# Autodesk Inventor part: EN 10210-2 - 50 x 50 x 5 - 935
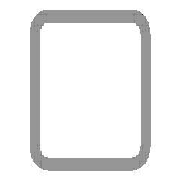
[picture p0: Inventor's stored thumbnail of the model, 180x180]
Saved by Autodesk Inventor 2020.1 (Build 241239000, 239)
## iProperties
IsCustomPart: 1
_CCFamilyMember: 16
_CCFamilyDisplayName: DIN EN 10210-2 (USAS B17.1 quadratisch) - Rohrleitung — In Klammern angegebene Größen wurden aufgehoben
_FrameMemberDoc: Frame Member File
_Version: 15.0.0
_GetPNFromCC: 1
Created: 2019-10
Part Number: EN 10210-2 - 50 x 50 x 5 - 935
Material: Stahl, weich
Description: Rohrleitung
Document SubType Name: Modeling
Standard: DIN
Designer: lutzd
Standard Revision: 2006-07
Standards Organization: DIN
Language: de-DE
Size Designation: 50 x 50 x 5
Categories: <MemberInstance><Categories><Category DisplayName="Profile" InternalName="089c4875-fa83-4c05-b084-43b9cc11f5ed" Mnemonic="GRDR"><CategoryParameter DisplayName="
Stock Number: 50 x 50 x 5
Mass: 6406.16 g
Surface Area: 3183.51 cm^2
Volume: 816.071 cm^3
Density: 7.85 g/cm^3
Appearance: Halbpoliert
G_L: 935,000 mm
G_W: 50,000 mm
G_H: 50,000 mm
Dimensions: 50x50x935 mm
Mass: 6,406 kg
DocNumber: ADSK-014086
Folder: .
+DC350E34-C48C-440D-B476-852694BBE631+SCHNITTDETAIL1: Schnittwinkel 90,00 grd
+4DCEFB5E-3CB5-4DBE-9410-B38ADCC61D04+SCHNITTDETAIL2: Schnittwinkel 90,00 grd
Title: Profil-Bauteil
Author: lutzd
Revision Number: -
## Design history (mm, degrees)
node "Startebene"
node "Endebene"
sketch "Skizze"
  geometry: L1 (-25, -17.5)-(-25, 17.5); L2 (-17.5, 25)-(17.5, 25); L3 (25, 17.5)-(25, -17.5); L4 (17.5, -25)-(-17.5, -25); L5 (-15, 20)-(15, 20); L6 (20, 15)-(20, -15); L7 (15, -20)-(-15, -20); L8 (-20, -15)-(-20, 15); L9 (0, 37.175)-(0, -37.175) reference; L10 (-37.175, 0)-(37.175, 0) reference; A1 r 7.5 centre (-17.5, -17.5) between (-25, -17.5) and (-17.5, -25); A2 r 7.5 centre (-17.5, 17.5) between (-17.5, 25) and (-25, 17.5); A3 r 7.5 centre (17.5, 17.5) between (25, 17.5) and (17.5, 25); A4 r 7.5 centre (17.5, -17.5) between (17.5, -25) and (25, -17.5); A5 r 5 centre (-15, -15) between (-20, -15) and (-15, -20); A6 r 5 centre (-15, 15) between (-15, 20) and (-20, 15); A7 r 5 centre (15, 15) between (20, 15) and (15, 20); A8 r 5 centre (15, -15) between (15, -20) and (20, -15)
  constraints: 16 end point, 16 point on circle, 16 tangent, 8 centre point, 6 equal radius, 4 parallel, 2 perpendicular, 2 other
  dimensions: "d7" = 7.5 radius of A1 (= G_IR); "d10" = 50 distance between parallel lines of L2 L4 (= G_H); "d11" = 50 distance between parallel lines of L1 L3 (= G_W); "d12" = 5 distance between parallel lines of L3 L6 (= G_T); "d15" = 25 distance between parallel lines of L2 L10 (= 0.5 x d10); "d16" = 25 distance between parallel lines of L9 L3 (= 0.5 x d11); "d19" = 5 radius of A5 (= G_T); "d20" = 5 distance between parallel lines of L4 L7 (= G_T)
extrude "Körper" new body sketch "Skizze" stored distance "d3" = 935 (= G_L); taper "d4" = 0 deg
node "Driven Length"
  sketch "Sketch3"
    geometry: L1 (0, 0)-(10, 0) reference
    constraints: 2 end point, 1 horizontal
  workplane "Work Plane3"
  sketch "Sketch4"
    geometry: L1 (-2, 25)-(12, 25) reference; L2 (-2, 960)-(12, 960) reference
    dimensions: "d18" = 935 distance between parallel lines of L1 L2 (derived)
workplane "Arbeitsebene4"
feature "Trennen1"
workplane "Arbeitsebene5"
feature "Trennen2"
sketch "Skizze5"
  geometry: L1 (0, 935)-(-35, 935) reference; L2 (-17.5, 935)-(-17.5, 806); 3 further points
  constraints: 4 end point, 1 coincident, 1 horizontal, 1 midpoint, 1 point on line, 1 vertical, 2 other
  dimensions: "d21" = 34 distance from line of L1 point (-17.5, 901); "d22" = 95 distance of point (-17.5, 806) point (-17.5, 901)
hole "Bohrung1" sketch "Skizze5" at (-17.5, 806), (-17.5, 901) diameter "d23" = 6.647; stored, may be unused: countersink angle "d27" = 90 deg, drill point angle "d29" = 0 deg; dims "d24" = 16, "d25" = 4, "d26" = 2, "d28" = 8
body "Solid1"
other parameters: "G_W" = 50 [user parameter; used in 1 equation term], "G_H" = 50 [user parameter; used in 1 equation term], "G_T" = 5 [user parameter; used in 3 equation terms], "G_IR" = 7.5 [user parameter; used in 1 equation term], "G_L" = 935 (= d18) [user parameter; used in 1 equation term], "G_OFFSET_START" = -25 [user parameter; used in 1 equation term], "G_OFFSET_END" = -25 [user parameter; used in 1 equation term], "d13" = 25 (= -G_OFFSET_START), "B_L" = 985 [user parameter; used in 1 equation term], "d17" = 90 deg
